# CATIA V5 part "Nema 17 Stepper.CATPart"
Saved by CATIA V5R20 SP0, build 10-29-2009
Part number: Nema17
Source: Unknown
Bounding box of the stored display mesh (mm): x -21.15 to 26.35, y -24.9 to 44.9, z -21.15 to 21.15
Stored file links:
  C:\Users\Ikarus\OneDrive - FH JOANNEUM\BAC - Arbeit 1\CAD Modell\CAD-Modell-Step files\stepper\Nema 17 Stepper.CATPart
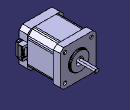
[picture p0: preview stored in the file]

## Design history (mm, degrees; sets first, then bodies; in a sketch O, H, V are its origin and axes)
Body1 "Solid1" (main body)
  Solid1: solid without history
